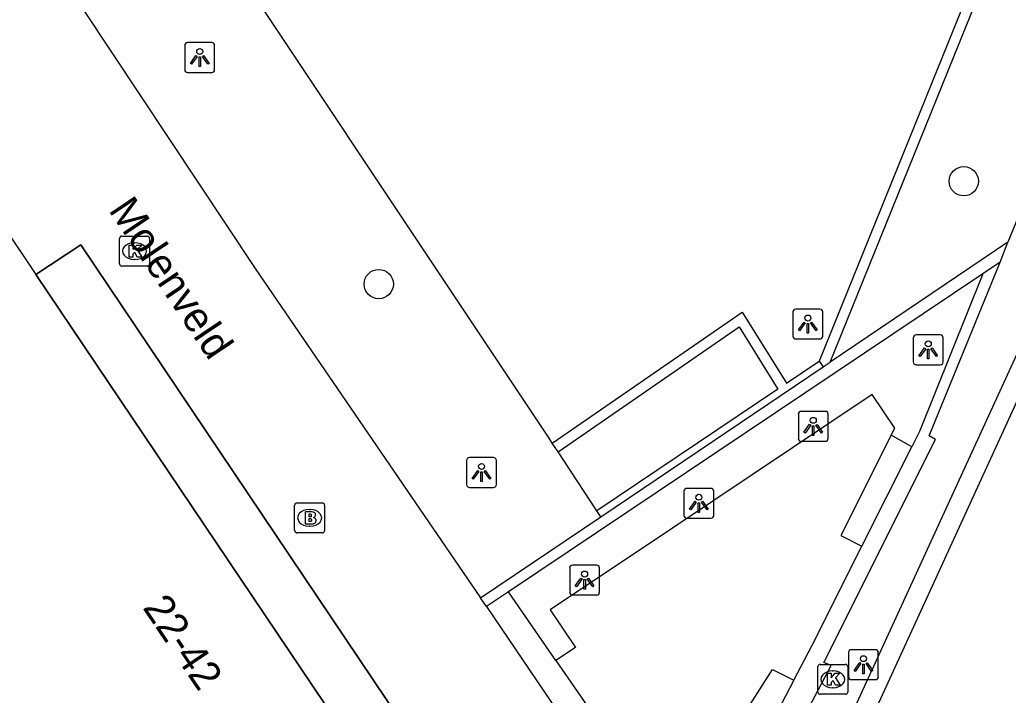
# Model space of a CAD drawing. Extents: x 161087 to 161922, y 382574 to 383873.
# Drawn here: x 161703.46 to 161736.47, y 382966.64 to 382989.18 of the extents above; entities that cross this region are included whole.
import ezdxf

# ---------------------------------------------------------------- set-up
doc = ezdxf.new("R2010")
doc.units = 0
for name, color, linetype in [('IMGEO_Boom', 7, 'Continuous'), ('IMGEO_Brandkraan', 7, 'Continuous'), ('IMGEO_Groenvoorziening', 7, 'Continuous'), ('IMGEO_Haag', 7, 'Continuous'), ('IMGEO_Kolk', 7, 'Continuous'), ('IMGEO_Lichtpunt', 7, 'Continuous'), ('IMGEO_Muur', 7, 'Continuous'), ('IMGEO_Openbare_ruimte_label', 7, 'Continuous'), ('IMGEO_Pand', 7, 'Continuous'), ('IMGEO_Pand_nummerreeks', 7, 'Continuous'), ('IMGEO_Pand_overbouw', 7, 'Continuous'), ('IMGEO_Rijbaan_lokaal_open', 7, 'Continuous'), ('IMGEO_Voetgangersgebied_open', 7, 'Continuous'), ('IMGEO_Voetpad_op_trap', 7, 'Continuous'), ('IMGEO_Voetpad_open', 7, 'Continuous')]:
    doc.layers.add(name, color=color, linetype=linetype)

msp = doc.modelspace()

# ---------------------------------------------------------------- linework, layer by layer
at = {"layer": 'IMGEO_Boom'}
for centre in [(161734.983, 382983.795), (161715.448, 382980.362)]:
    msp.add_circle(centre, 0.489, dxfattribs=at)
at = {"layer": 'IMGEO_Brandkraan'}
for p, q in [((161712.64, 382972.133), (161712.64, 382972.985)), ((161712.715, 382973.059), (161713.567, 382973.059)), ((161713.641, 382972.985), (161713.641, 382972.133)), ((161713.128, 382972.839), (161713.153, 382972.839)), ((161713.567, 382972.059), (161712.715, 382972.059)), ((161713.151, 382972.279), (161713.126, 382972.279))]:
    msp.add_line(p, q, dxfattribs=at)
for points in [[(161712.64, 382972.133), (161712.64, 382972.985)], [(161712.715, 382973.059), (161713.567, 382973.059)], [(161713.641, 382972.985), (161713.641, 382972.133)], [(161712.988, 382972.759), (161712.988, 382972.359), (161713.201, 382972.359)], [(161713.219, 382972.759), (161712.988, 382972.759)], [(161713.167, 382972.678), (161713.113, 382972.678), (161713.113, 382972.602)], [(161713.113, 382972.602), (161713.166, 382972.602)], [(161713.175, 382972.526), (161713.113, 382972.526), (161713.113, 382972.445)], [(161713.113, 382972.445), (161713.175, 382972.445)], [(161713.567, 382972.059), (161712.715, 382972.059)]]:
    msp.add_lwpolyline(points, dxfattribs=at)
for centre, radius, start, end in [((161712.717, 382972.983), 0.0765, 91.552, 178.448), ((161712.717, 382972.983), 0.0765, 91.552, 178.448), ((161713.565, 382972.983), 0.0765, 1.552, 88.448), ((161713.565, 382972.983), 0.0765, 1.552, 88.448), ((161713.168, 382972.64), 0.0379, 267.8285, 90.9355), ((161713.223, 382972.614), 0.145, 59.4692, 91.5367), ((161713.248, 382972.661), 0.0922, 285.5137, 58.1501), ((161713.176, 382972.485), 0.0404, 269.8759, 90.5077), ((161713.207, 382972.61), 0.251, 268.6676, 293.5347), ((161713.253, 382972.469), 0.105, 301.3115, 78.989), ((161712.717, 382972.135), 0.0765, 181.552, 268.448), ((161712.717, 382972.135), 0.0765, 181.552, 268.448), ((161713.565, 382972.135), 0.0765, 271.552, 358.448), ((161713.565, 382972.135), 0.0765, 271.552, 358.448)]:
    msp.add_arc(centre, radius, start, end, dxfattribs=at)
for centre, major_axis, ratio, start_param, end_param in [((161713.127, 382972.559), (-0.387, 0.002), 0.722429, 4.712389, 7.853982), ((161713.152, 382972.559), (-0.39, 0.002), 0.717154, 1.570796, 4.712389)]:
    msp.add_ellipse(centre, major_axis=major_axis, ratio=ratio, start_param=start_param, end_param=end_param, dxfattribs=at)
at = {"layer": 'IMGEO_Groenvoorziening'}
msp.add_lwpolyline([(161733.247, 382974.93), (161732.561, 382975.322)], dxfattribs=at)
at = {"layer": 'IMGEO_Haag'}
for points in [[(161747.272, 383020.049), (161741.948, 383006.903), (161730.157, 382977.79)], [(161730.52, 382977.756), (161742.9, 383008.325), (161745.252, 383014.216), (161747.477, 383019.703)]]:
    msp.add_lwpolyline(points, dxfattribs=at)
at = {"layer": 'IMGEO_Kolk'}
for p, q in [((161706.793, 382981.037), (161706.793, 382981.889)), ((161706.868, 382981.963), (161707.72, 382981.963)), ((161707.794, 382981.889), (161707.794, 382981.037)), ((161707.281, 382981.743), (161707.306, 382981.743)), ((161707.72, 382980.963), (161706.868, 382980.963)), ((161707.304, 382981.183), (161707.279, 382981.183)), ((161730.112, 382966.744), (161730.112, 382967.596)), ((161730.187, 382967.67), (161731.039, 382967.67)), ((161730.6, 382967.45), (161730.625, 382967.45)), ((161731.113, 382967.596), (161731.113, 382966.744)), ((161730.623, 382966.89), (161730.598, 382966.89)), ((161731.039, 382966.67), (161730.187, 382966.67))]:
    msp.add_line(p, q, dxfattribs=at)
for points in [[(161706.793, 382981.037), (161706.793, 382981.889)], [(161706.868, 382981.963), (161707.72, 382981.963)], [(161707.794, 382981.889), (161707.794, 382981.037)], [(161707.114, 382981.663), (161707.237, 382981.663), (161707.237, 382981.512), (161707.367, 382981.663), (161707.531, 382981.663), (161707.385, 382981.512), (161707.538, 382981.263), (161707.386, 382981.263), (161707.301, 382981.427), (161707.237, 382981.36), (161707.237, 382981.263), (161707.114, 382981.263), (161707.114, 382981.663)], [(161707.72, 382980.963), (161706.868, 382980.963)], [(161730.112, 382966.744), (161730.112, 382967.596)], [(161730.187, 382967.67), (161731.039, 382967.67)], [(161730.433, 382967.37), (161730.556, 382967.37), (161730.556, 382967.219), (161730.686, 382967.37), (161730.85, 382967.37), (161730.704, 382967.219), (161730.857, 382966.97), (161730.705, 382966.97), (161730.62, 382967.134), (161730.556, 382967.067), (161730.556, 382966.97), (161730.433, 382966.97), (161730.433, 382967.37)], [(161731.113, 382967.596), (161731.113, 382966.744)], [(161731.039, 382966.67), (161730.187, 382966.67)]]:
    msp.add_lwpolyline(points, dxfattribs=at)
for centre, start, end in [((161706.87, 382981.887), 91.552, 178.448), ((161706.87, 382981.887), 91.552, 178.448), ((161707.718, 382981.887), 1.552, 88.448), ((161707.718, 382981.887), 1.552, 88.448), ((161706.87, 382981.039), 181.552, 268.448), ((161706.87, 382981.039), 181.552, 268.448), ((161707.718, 382981.039), 271.552, 358.448), ((161707.718, 382981.039), 271.552, 358.448), ((161730.189, 382967.594), 91.552, 178.448), ((161730.189, 382967.594), 91.552, 178.448), ((161731.037, 382967.594), 1.552, 88.448), ((161731.037, 382967.594), 1.552, 88.448), ((161730.189, 382966.746), 181.552, 268.448), ((161730.189, 382966.746), 181.552, 268.448), ((161731.037, 382966.746), 271.552, 358.448), ((161731.037, 382966.746), 271.552, 358.448)]:
    msp.add_arc(centre, 0.0765, start, end, dxfattribs=at)
for centre, major_axis, ratio, start_param, end_param in [((161707.28, 382981.463), (-0.387, 0.002), 0.722429, 4.712389, 7.853982), ((161707.305, 382981.463), (-0.39, 0.002), 0.717154, 1.570796, 4.712389), ((161730.599, 382967.17), (-0.387, 0.002), 0.722429, 4.712389, 7.853982), ((161730.624, 382967.17), (-0.39, 0.002), 0.717154, 1.570796, 4.712389)]:
    msp.add_ellipse(centre, major_axis=major_axis, ratio=ratio, start_param=start_param, end_param=end_param, dxfattribs=at)
at = {"layer": 'IMGEO_Lichtpunt'}
for p, q in [((161708.971, 382988.326), (161708.971, 382987.519)), ((161708.971, 382988.326), (161708.971, 382987.519)), ((161709.873, 382988.421), (161709.065, 382988.421)), ((161709.873, 382988.421), (161709.065, 382988.421)), ((161709.967, 382987.519), (161709.967, 382988.326)), ((161709.967, 382987.519), (161709.967, 382988.326)), ((161709.065, 382987.425), (161709.873, 382987.425)), ((161709.065, 382987.425), (161709.873, 382987.425)), ((161729.279, 382979.431), (161729.279, 382978.624)), ((161729.279, 382979.431), (161729.279, 382978.624)), ((161730.181, 382979.526), (161729.373, 382979.526)), ((161730.181, 382979.526), (161729.373, 382979.526)), ((161730.275, 382978.624), (161730.275, 382979.431)), ((161730.275, 382978.624), (161730.275, 382979.431)), ((161734.202, 382978.664), (161733.394, 382978.664)), ((161734.202, 382978.664), (161733.394, 382978.664)), ((161729.373, 382978.53), (161730.181, 382978.53)), ((161729.373, 382978.53), (161730.181, 382978.53)), ((161733.3, 382978.569), (161733.3, 382977.762)), ((161733.3, 382978.569), (161733.3, 382977.762)), ((161734.296, 382977.762), (161734.296, 382978.569)), ((161734.296, 382977.762), (161734.296, 382978.569)), ((161733.394, 382977.668), (161734.202, 382977.668)), ((161733.394, 382977.668), (161734.202, 382977.668)), ((161729.46, 382976.017), (161729.46, 382975.21)), ((161729.46, 382976.017), (161729.46, 382975.21)), ((161730.362, 382976.112), (161729.554, 382976.112)), ((161730.362, 382976.112), (161729.554, 382976.112)), ((161730.456, 382975.21), (161730.456, 382976.017)), ((161730.456, 382975.21), (161730.456, 382976.017)), ((161729.554, 382975.116), (161730.362, 382975.116)), ((161729.554, 382975.116), (161730.362, 382975.116)), ((161718.381, 382974.476), (161718.381, 382973.669)), ((161718.381, 382974.476), (161718.381, 382973.669)), ((161719.283, 382974.571), (161718.475, 382974.571)), ((161719.283, 382974.571), (161718.475, 382974.571)), ((161719.377, 382973.669), (161719.377, 382974.476)), ((161719.377, 382973.669), (161719.377, 382974.476)), ((161718.475, 382973.575), (161719.283, 382973.575)), ((161718.475, 382973.575), (161719.283, 382973.575)), ((161725.64, 382973.449), (161725.64, 382972.642)), ((161725.64, 382973.449), (161725.64, 382972.642)), ((161726.542, 382973.544), (161725.734, 382973.544)), ((161726.542, 382973.544), (161725.734, 382973.544)), ((161726.636, 382972.642), (161726.636, 382973.449)), ((161726.636, 382972.642), (161726.636, 382973.449)), ((161725.734, 382972.548), (161726.542, 382972.548)), ((161725.734, 382972.548), (161726.542, 382972.548)), ((161721.824, 382970.886), (161721.824, 382970.079)), ((161721.824, 382970.886), (161721.824, 382970.079)), ((161722.726, 382970.981), (161721.918, 382970.981)), ((161722.726, 382970.981), (161721.918, 382970.981)), ((161722.82, 382970.079), (161722.82, 382970.886)), ((161722.82, 382970.079), (161722.82, 382970.886)), ((161721.918, 382969.985), (161722.726, 382969.985)), ((161721.918, 382969.985), (161722.726, 382969.985)), ((161731.135, 382968.062), (161731.135, 382967.255)), ((161731.135, 382968.062), (161731.135, 382967.255)), ((161732.037, 382968.157), (161731.229, 382968.157)), ((161732.037, 382968.157), (161731.229, 382968.157)), ((161732.131, 382967.255), (161732.131, 382968.062)), ((161732.131, 382967.255), (161732.131, 382968.062)), ((161731.229, 382967.161), (161732.037, 382967.161)), ((161731.229, 382967.161), (161732.037, 382967.161))]:
    msp.add_line(p, q, dxfattribs=at)
for points in [[(161709.345, 382987.99), (161709.384, 382987.962), (161709.196, 382987.7), (161709.158, 382987.727), (161709.345, 382987.99)], [(161709.447, 382987.942), (161709.494, 382987.942), (161709.494, 382987.62), (161709.447, 382987.62), (161709.447, 382987.942)], [(161709.557, 382987.962), (161709.595, 382987.989), (161709.782, 382987.727), (161709.743, 382987.699), (161709.557, 382987.962)], [(161729.653, 382979.095), (161729.692, 382979.067), (161729.504, 382978.805), (161729.466, 382978.832), (161729.653, 382979.095)], [(161729.755, 382979.047), (161729.802, 382979.047), (161729.802, 382978.725), (161729.755, 382978.725), (161729.755, 382979.047)], [(161729.865, 382979.067), (161729.903, 382979.094), (161730.09, 382978.832), (161730.051, 382978.804), (161729.865, 382979.067)], [(161733.674, 382978.233), (161733.713, 382978.205), (161733.525, 382977.943), (161733.487, 382977.97), (161733.674, 382978.233)], [(161733.776, 382978.185), (161733.823, 382978.185), (161733.823, 382977.863), (161733.776, 382977.863), (161733.776, 382978.185)], [(161733.886, 382978.205), (161733.924, 382978.232), (161734.111, 382977.97), (161734.072, 382977.942), (161733.886, 382978.205)], [(161729.834, 382975.681), (161729.873, 382975.653), (161729.685, 382975.391), (161729.647, 382975.418), (161729.834, 382975.681)], [(161729.936, 382975.633), (161729.983, 382975.633), (161729.983, 382975.311), (161729.936, 382975.311), (161729.936, 382975.633)], [(161730.046, 382975.653), (161730.084, 382975.68), (161730.271, 382975.418), (161730.232, 382975.39), (161730.046, 382975.653)], [(161718.755, 382974.14), (161718.794, 382974.112), (161718.606, 382973.85), (161718.568, 382973.877), (161718.755, 382974.14)], [(161718.857, 382974.092), (161718.904, 382974.092), (161718.904, 382973.77), (161718.857, 382973.77), (161718.857, 382974.092)], [(161718.967, 382974.112), (161719.005, 382974.139), (161719.192, 382973.877), (161719.153, 382973.849), (161718.967, 382974.112)], [(161726.014, 382973.113), (161726.053, 382973.085), (161725.865, 382972.823), (161725.827, 382972.85), (161726.014, 382973.113)], [(161726.116, 382973.065), (161726.163, 382973.065), (161726.163, 382972.743), (161726.116, 382972.743), (161726.116, 382973.065)], [(161726.226, 382973.085), (161726.264, 382973.112), (161726.451, 382972.85), (161726.412, 382972.822), (161726.226, 382973.085)], [(161722.198, 382970.55), (161722.237, 382970.522), (161722.049, 382970.26), (161722.011, 382970.287), (161722.198, 382970.55)], [(161722.3, 382970.502), (161722.347, 382970.502), (161722.347, 382970.18), (161722.3, 382970.18), (161722.3, 382970.502)], [(161722.41, 382970.522), (161722.448, 382970.549), (161722.635, 382970.287), (161722.596, 382970.259), (161722.41, 382970.522)], [(161731.509, 382967.726), (161731.548, 382967.698), (161731.36, 382967.436), (161731.322, 382967.463), (161731.509, 382967.726)], [(161731.721, 382967.698), (161731.759, 382967.725), (161731.946, 382967.463), (161731.907, 382967.435), (161731.721, 382967.698)], [(161731.611, 382967.678), (161731.658, 382967.678), (161731.658, 382967.356), (161731.611, 382967.356), (161731.611, 382967.678)]]:
    msp.add_lwpolyline(points, dxfattribs=at)
for centre in [(161709.47, 382988.124), (161729.778, 382979.229), (161733.799, 382978.367), (161729.959, 382975.815), (161718.88, 382974.274), (161726.139, 382973.247), (161722.323, 382970.684), (161731.634, 382967.86)]:
    msp.add_circle(centre, 0.0994, dxfattribs=at)
for centre, start, end in [((161709.065, 382988.326), 90, 180), ((161709.065, 382988.326), 90, 180), ((161709.873, 382988.326), 0, 90), ((161709.873, 382988.326), 0, 90), ((161709.065, 382987.519), 180, 270), ((161709.065, 382987.519), 180, 270), ((161709.873, 382987.519), 270, 0), ((161709.873, 382987.519), 270, 360), ((161729.373, 382979.431), 90, 180), ((161729.373, 382979.431), 90, 180), ((161730.181, 382979.431), 0, 90), ((161730.181, 382979.431), 0, 90), ((161729.373, 382978.624), 180, 270), ((161729.373, 382978.624), 180, 270), ((161730.181, 382978.624), 270, 0), ((161730.181, 382978.624), 270, 360), ((161733.394, 382978.569), 90, 180), ((161733.394, 382978.569), 90, 180), ((161734.202, 382978.569), 0, 90), ((161734.202, 382978.569), 0, 90), ((161733.394, 382977.762), 180, 270), ((161733.394, 382977.762), 180, 270), ((161734.202, 382977.762), 270, 0), ((161734.202, 382977.762), 270, 360), ((161729.554, 382976.017), 90, 180), ((161729.554, 382976.017), 90, 180), ((161730.362, 382976.017), 0, 90), ((161730.362, 382976.017), 0, 90), ((161729.554, 382975.21), 180, 270), ((161729.554, 382975.21), 180, 270), ((161730.362, 382975.21), 270, 0), ((161730.362, 382975.21), 270, 360), ((161718.475, 382974.476), 90, 180), ((161718.475, 382974.476), 90, 180), ((161719.283, 382974.476), 0, 90), ((161719.283, 382974.476), 0, 90), ((161718.475, 382973.669), 180, 270), ((161718.475, 382973.669), 180, 270), ((161719.283, 382973.669), 270, 0), ((161719.283, 382973.669), 270, 360), ((161725.734, 382973.449), 90, 180), ((161725.734, 382973.449), 90, 180), ((161726.542, 382973.449), 0, 90), ((161726.542, 382973.449), 0, 90), ((161725.734, 382972.642), 180, 270), ((161725.734, 382972.642), 180, 270), ((161726.542, 382972.642), 270, 0), ((161726.542, 382972.642), 270, 360), ((161721.918, 382970.886), 90, 180), ((161721.918, 382970.886), 90, 180), ((161722.726, 382970.886), 0, 90), ((161722.726, 382970.886), 0, 90), ((161721.918, 382970.079), 180, 270), ((161721.918, 382970.079), 180, 270), ((161722.726, 382970.079), 270, 0), ((161722.726, 382970.079), 270, 360), ((161731.229, 382968.062), 90, 180), ((161731.229, 382968.062), 90, 180), ((161732.037, 382968.062), 0, 90), ((161732.037, 382968.062), 0, 90), ((161731.229, 382967.255), 180, 270), ((161731.229, 382967.255), 180, 270), ((161732.037, 382967.255), 270, 0), ((161732.037, 382967.255), 270, 360)]:
    msp.add_arc(centre, 0.0946, start, end, dxfattribs=at)
at = {"layer": 'IMGEO_Muur'}
for points in [[(161683.751, 382919.765), (161684.007, 382919.846), (161684.124, 382919.605), (161692.853, 382925.234), (161726.106, 382957.452), (161726.799, 382959.834), (161730.734, 382964.893), (161739.867, 382984.771), (161740.681, 382986.664), (161757.921, 383030.385)], [(161758.426, 383029.994), (161740.45, 382984.512), (161731.348, 382964.654), (161727.347, 382959.466), (161726.694, 382957.106), (161693.352, 382924.798), (161684.407, 382919.024), (161684.56, 382918.709)], [(161736.46, 382981.759), (161730.52, 382977.756)], [(161736.2, 382981.092), (161736.46, 382981.759)], [(161736.2, 382981.092), (161735.617, 382980.701)], [(161735.617, 382980.701), (161719.778, 382970.089)], [(161721.244, 382975.057), (161727.583, 382979.426), (161729.066, 382977.055), (161730.157, 382977.79)], [(161721.436, 382974.765), (161727.48, 382978.93), (161728.776, 382976.859), (161722.735, 382972.789)], [(161722.863, 382972.595), (161730.29, 382977.601)], [(161730.157, 382977.79), (161730.29, 382977.601)], [(161730.29, 382977.601), (161730.52, 382977.756)], [(161721.436, 382974.765), (161721.244, 382975.057)], [(161722.863, 382972.595), (161722.735, 382972.789)], [(161718.85, 382969.89), (161722.863, 382972.595)], [(161719.778, 382970.089), (161719.047, 382969.599)], [(161719.047, 382969.599), (161718.85, 382969.89)]]:
    msp.add_lwpolyline(points, dxfattribs=at)
at = {"layer": 'IMGEO_Pand'}
for points in [[(161702.92, 382982.299), (161704, 382980.687)], [(161718.876, 382958.573), (161704, 382980.687)]]:
    msp.add_lwpolyline(points, dxfattribs=at)
at = {"layer": 'IMGEO_Pand_overbouw'}
msp.add_lwpolyline([(161718.876, 382958.573), (161720.371, 382959.557), (161705.503, 382981.675), (161704, 382980.687)], close=True, dxfattribs=at)
at = {"layer": 'IMGEO_Rijbaan_lokaal_open'}
for points in [[(161701.717, 382995.339), (161711.324, 382980.879), (161718.85, 382969.89)], [(161704, 382980.687), (161705.503, 382981.675), (161720.371, 382959.557), (161718.876, 382958.573)], [(161719.047, 382969.599), (161725.511, 382960.056)]]:
    msp.add_lwpolyline(points, dxfattribs=at)
at = {"layer": 'IMGEO_Voetgangersgebied_open'}
for points in [[(161732.561, 382975.322), (161732.677, 382975.552), (161731.922, 382976.676), (161725.256, 382972.218), (161721.175, 382969.488), (161722.014, 382968.233), (161721.361, 382967.797)], [(161732.561, 382975.322), (161730.876, 382971.971), (161731.578, 382971.611)], [(161724.229, 382963.645), (161724.832, 382964.052), (161725.635, 382962.86), (161728.596, 382967.502), (161729.308, 382967.145)]]:
    msp.add_lwpolyline(points, dxfattribs=at)
at = {"layer": 'IMGEO_Voetpad_op_trap'}
for points in [[(161735.617, 382980.701), (161733.506, 382975.444), (161733.247, 382974.93)], [(161731.578, 382971.611), (161733.247, 382974.93)], [(161729.308, 382967.145), (161729.908, 382968.29), (161731.578, 382971.611)], [(161721.361, 382967.797), (161719.778, 382970.089)], [(161721.361, 382967.797), (161724.229, 382963.645)], [(161729.308, 382967.145), (161728.65, 382965.889), (161727.362, 382963.805), (161725.699, 382961.516), (161724.229, 382963.645)]]:
    msp.add_lwpolyline(points, dxfattribs=at)
at = {"layer": 'IMGEO_Voetpad_open'}
for points in [[(161753.87, 383025.593), (161746.557, 383006.929), (161739.215, 382988.479), (161736.46, 382981.759)], [(161721.244, 382975.057), (161721.113, 382975.256), (161707.658, 382995.446)], [(161725.511, 382960.056), (161725.616, 382959.902), (161728.111, 382963.342), (161729.404, 382965.435), (161730.554, 382967.627), (161730.313, 382967.732), (161734.042, 382975.175), (161733.826, 382975.297), (161736.2, 382981.092)], [(161722.735, 382972.789), (161721.436, 382974.765)]]:
    msp.add_lwpolyline(points, dxfattribs=at)

# ---------------------------------------------------------------- texts
at = {"layer": 'IMGEO_Openbare_ruimte_label'}
msp.add_text('Molenveld', height=1, rotation=303.9125, dxfattribs=at).set_placement((161706.407, 382982.828))
at = {"layer": 'IMGEO_Pand_nummerreeks'}
msp.add_text('22-42', height=1, rotation=303.9548, dxfattribs=at).set_placement((161707.545, 382969.562))

doc.saveas('drawing.dxf')
